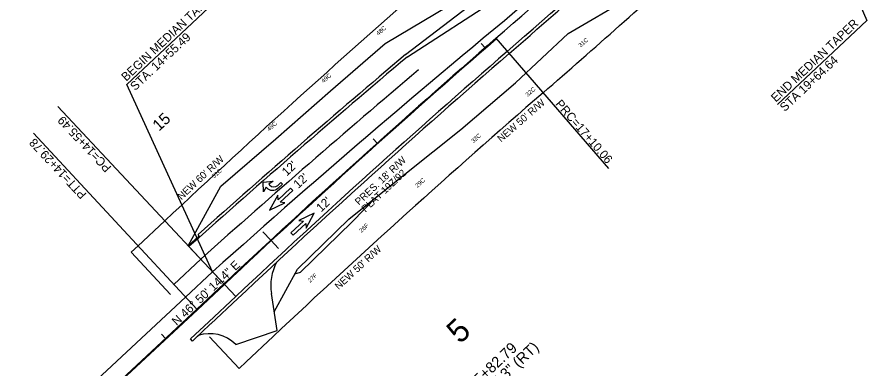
# Model space of a CAD drawing. Extents: x 1623239 to 1625698, y 1118659 to 1120751.
# Drawn here: x 1623812 to 1624403, y 1119168 to 1119413 of the extents above; entities that cross this region are included whole.
import ezdxf

# ---------------------------------------------------------------- set-up
doc = ezdxf.new("R2010")
doc.units = 0
for name, color, linetype in [('RD_EX_DV_TX_Prop', 7, 'Continuous'), ('RD_EX_RW_TX', 7, 'Continuous'), ('RD_HC_Cl', 7, 'Continuous'), ('RD_HC_CL_Rel', 7, 'Continuous'), ('RD_HC_Data', 7, 'Continuous'), ('RD_HC_Data_Tic', 7, 'Continuous'), ('RD_HC_TX_Sta50', 7, 'Continuous'), ('RD_PD_CstnLmt', 7, 'Continuous'), ('RD_PD_CstnLmt_TX', 7, 'Continuous'), ('RD_PD_DR_ErosCtrl', 7, 'Continuous'), ('RD_PD_Driveway', 7, 'Continuous'), ('RD_PD_Final_LnLine', 7, 'Continuous'), ('RD_PD_Final_TrvlWay', 7, 'Continuous'), ('RD_PD_Final_TX', 7, 'Continuous'), ('RD_PD_PaintMed', 7, 'Continuous'), ('RD_PD_PaveShd', 7, 'Continuous'), ('RD_PD_RW', 7, 'Continuous'), ('RD_PD_RW_TX', 7, 'Continuous')]:
    doc.layers.add(name, color=color, linetype=linetype)

# ---------------------------------------------------------------- blocks, each defined once
blk = doc.blocks.new('TARROW')
at = {"layer": 'RD_PD_Final_LnLine'}
for p, q in [((-3.29, -2.67), (-1.05, -2.34)), ((-1.05, -2.34), (-1.05, -3.09)), ((0.62, -3.09), (0.62, -2.5)), ((0.62, -2.5), (2.87, -3.17)), ((-3.3, -5.34), (-5.38, -5.34)), ((-5.38, -5.34), (-5.38, -6.34)), ((-5.38, -6.34), (-2.63, -6.34))]:
    blk.add_line(p, q, dxfattribs=at)
blk.add_lwpolyline([(2.87, -3.17), (0, 0), (-3.29, -2.67)], dxfattribs=at)
for centre, radius in [((-3.3, -3.09), 2.25), ((-2.63, -3.09), 3.25)]:
    blk.add_arc(centre, radius, 270, 0, dxfattribs=at)
blk = doc.blocks.new('RA Curved')
at = {"layer": 'RD_PD_Final_LnLine', "xscale": 1.0799984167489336, "yscale": -1.0799984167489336}
blk.add_blockref('TARROW', (6.14, -5.79), dxfattribs=at)

msp = doc.modelspace()

# ---------------------------------------------------------------- linework, layer by layer
at = {"layer": 'RD_HC_Cl'}
for p, q in [((1623937.25, 1119209.79), (1623956, 1119227.38)), ((1623608.84, 1118904.32), (1623937.25, 1119209.79))]:
    msp.add_line(p, q, dxfattribs=at)
at = {"layer": 'RD_HC_CL_Rel'}
for centre, start, end in [((1619901.34, 1124294.89), 310.911734, 313.16267), ((1628388.79, 1114500.77), 130.911734, 133.16267)]:
    msp.add_arc(centre, 6480, start, end, dxfattribs=at)
at = {"layer": 'RD_HC_Data'}
for p, q in [((1624145.06, 1119397.83), (1624223.3, 1119307.55)), ((1623956, 1119227.38), (1623840.61, 1119350.42)), ((1623937.25, 1119209.79), (1623823.59, 1119331.99))]:
    msp.add_line(p, q, dxfattribs=at)
at = {"layer": 'RD_HC_Data_Tic'}
for p, q in [((1624137.46, 1119391.24), (1624134.84, 1119394.26)), ((1624062.5, 1119325.05), (1624059.83, 1119328.03)), ((1623988.57, 1119257.72), (1623983.14, 1119263.59)), ((1623994, 1119251.84), (1623988.57, 1119257.72)), ((1623915.44, 1119189.51), (1623912.72, 1119192.44))]:
    msp.add_line(p, q, dxfattribs=at)
at = {"layer": 'RD_PD_CstnLmt'}
for p, q in [((1624195.36, 1119401.06), (1624239.51, 1119427.03)), ((1624068.03, 1119394.33), (1624112.11, 1119420.41)), ((1624158.63, 1119366.89), (1624195.36, 1119401.06)), ((1624029.97, 1119361.33), (1624068.03, 1119394.33)), ((1624120.76, 1119334.61), (1624158.63, 1119366.89)), ((1623992.2, 1119327.98), (1624029.97, 1119361.33)), ((1624081.79, 1119303.54), (1624120.76, 1119334.61)), ((1623953.89, 1119295.21), (1623992.2, 1119327.98)), ((1624042.89, 1119272.33), (1624081.79, 1119303.54)), ((1623931.22, 1119253.8), (1623953.89, 1119295.21)), ((1624007.14, 1119237.64), (1624042.89, 1119272.33)), ((1623990.97, 1119207.92), (1624007.14, 1119237.64))]:
    msp.add_line(p, q, dxfattribs=at)
at = {"layer": 'RD_PD_DR_ErosCtrl'}
for p, q in [((1624044.98, 1119270.18), (1624062.34, 1119287.94)), ((1624009.23, 1119235.49), (1624044.98, 1119270.18)), ((1624005.3, 1119234.26), (1624009.23, 1119235.49))]:
    msp.add_line(p, q, dxfattribs=at)
at = {"layer": 'RD_PD_Driveway'}
for p, q in [((1623993, 1119194.95), (1623988.97, 1119220.61)), ((1623964.25, 1119185.27), (1623993, 1119194.95)), ((1623934.07, 1119187.72), (1623938.06, 1119191.43))]:
    msp.add_line(p, q, dxfattribs=at)
for centre, radius, start, end in [((1624023.55, 1119226.04), 35, 152.24678, 188.93213), ((1623946.33, 1119167.84), 25, 44.19823, 109.30284)]:
    msp.add_arc(centre, radius, start, end, dxfattribs=at)
at = {"layer": 'RD_PD_Final_TrvlWay'}
for p, q in [((1624083.51, 1119385), (1624168.16, 1119439.74)), ((1623964.21, 1119218.62), (1623931.23, 1119253.79)), ((1623945.46, 1119201.04), (1623964.21, 1119218.62)), ((1623932.71, 1119189.18), (1623945.42, 1119201.01))]:
    msp.add_line(p, q, dxfattribs=at)
for centre, radius, start, end in [((1619901.34, 1124294.89), 6492, 310.911734, 313.16267), ((1628388.79, 1114500.77), 6468, 130.911734, 133.16267), ((1628628.65, 1113993.92), 7051.39, 130.133764, 131.766919)]:
    msp.add_arc(centre, radius, start, end, dxfattribs=at)
at = {"layer": 'RD_PD_Final_TX'}
for p, q in [((1624334.12, 1119568.29), (1624402.92, 1119410.28)), ((1623888.54, 1119365.77), (1623958.44, 1119431.32)), ((1624340.72, 1119351.94), (1624402.92, 1119410.28)), ((1623948.13, 1119235.77), (1623888.54, 1119365.77)), ((1624002.39, 1119293.91), (1623993.64, 1119285.7)), ((1623995.17, 1119284.06), (1624003.93, 1119292.27)), ((1624003.93, 1119292.27), (1624002.39, 1119293.91)), ((1623993.42, 1119289), (1623987.73, 1119278.62)), ((1623993.64, 1119285.7), (1623993.42, 1119289)), ((1623987.73, 1119278.62), (1623998.45, 1119283.64)), ((1623998.45, 1119283.64), (1623995.17, 1119284.06)), ((1624018.76, 1119276.45), (1624008.04, 1119271.44)), ((1624013.07, 1119266.08), (1624018.76, 1119276.45)), ((1624011.32, 1119271.01), (1624002.56, 1119262.8)), ((1624004.1, 1119261.16), (1624012.86, 1119269.37)), ((1624008.04, 1119271.44), (1624011.32, 1119271.01)), ((1624012.86, 1119269.37), (1624013.07, 1119266.08)), ((1624002.56, 1119262.8), (1624004.1, 1119261.16))]:
    msp.add_line(p, q, dxfattribs=at)
at = {"layer": 'RD_PD_PaintMed'}
for p, q in [((1623921.17, 1119226.93), (1623939.92, 1119244.52)), ((1623929.38, 1119218.18), (1623948.13, 1119235.77)), ((1623937.59, 1119209.43), (1623956.34, 1119227.01)), ((1623812.34, 1119109.31), (1623929.42, 1119218.21)), ((1623820.51, 1119100.53), (1623937.59, 1119209.43))]:
    msp.add_line(p, q, dxfattribs=at)
for centre, radius, start, end in [((1628628.65, 1113993.92), 7027.39, 129.270481, 131.762152), ((1628388.79, 1114500.77), 6479.5, 130.911734, 133.16267), ((1628628.65, 1113993.92), 7039.39, 130.133764, 131.762152)]:
    msp.add_arc(centre, radius, start, end, dxfattribs=at)
at = {"layer": 'RD_PD_PaveShd'}
for p, q in [((1624082.22, 1119386.53), (1624161.82, 1119447.48)), ((1623931.22, 1119253.8), (1623938.73, 1119260.81)), ((1623938.73, 1119260.81), (1623938.01, 1119261.57)), ((1623946.83, 1119199.58), (1623965.58, 1119217.17)), ((1623934.07, 1119187.72), (1623946.78, 1119199.54)), ((1623934.07, 1119187.72), (1623932.71, 1119189.18))]:
    msp.add_line(p, q, dxfattribs=at)
for centre, radius, start, end in [((1619901.34, 1124294.89), 6494, 310.911734, 312.721401), ((1628628.65, 1113993.92), 7053.39, 130.133764, 131.683852), ((1628388.79, 1114500.77), 6466, 130.911734, 133.16267)]:
    msp.add_arc(centre, radius, start, end, dxfattribs=at)
at = {"layer": 'RD_PD_RW'}
for p, q in [((1623896.2, 1119253.56), (1623914.95, 1119271.14)), ((1623891.59, 1119249.27), (1623896.38, 1119253.73)), ((1623918.83, 1119219.98), (1623891.59, 1119249.27)), ((1623966.51, 1119168.72), (1623946.07, 1119190.69)), ((1623971.38, 1119173.25), (1623990.2, 1119190.91)), ((1623966.51, 1119168.72), (1623971.38, 1119173.25))]:
    msp.add_line(p, q, dxfattribs=at)
for centre, radius, start, end in [((1619901.34, 1124294.89), 6530, 310.911734, 312.151971), ((1628388.79, 1114500.77), 6540, 130.911734, 133.16267), ((1628388.79, 1114500.77), 6430, 130.911734, 133.16267)]:
    msp.add_arc(centre, radius, start, end, dxfattribs=at)

# ---------------------------------------------------------------- block references
at = {"layer": 'RD_PD_RW_TX', "xscale": 1.4999999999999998, "yscale": 1.5, "rotation": -136.8373301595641}
msp.add_blockref('RA Curved', (1623996, 1119298.05), dxfattribs=at)

# ---------------------------------------------------------------- texts
at = {"layer": 'RD_EX_DV_TX_Prop'}
msp.add_text('5', height=16, rotation=43.16267, dxfattribs=at).set_placement((1624120.03, 1119185.15))
at = {"layer": 'RD_EX_RW_TX'}
for s, p in [("PRES. 18' R/W", (1624049.88, 1119281.61)), ('PLAT 19Z/92', (1624054.44, 1119276.75))]:
    msp.add_text(s, height=5, rotation=43.16267, dxfattribs=at).set_placement(p)
at = {"layer": 'RD_HC_Data'}
for s, height, rotation, p in [('PRC=17+10.06', 6, 310.91173, (1624185.92, 1119352.03)), ('PC=14+55.49', 6, 133.16267, (1623878.17, 1119308.34)), ('PTT=14+29.78', 6, 132.92763, (1623860.98, 1119289.76)), ('N 46%%d 50\' 14.4" E', 6, 43.16267, (1623923.23, 1119198.02)), ('P.I. = 15+82.79', 7.5, 43.16267, (1624110.37, 1119135.08)), ('    = 2%%d 15\' 3" (RT)', 7.5, 43.16267, (1624117.21, 1119127.79))]:
    msp.add_text(s, height=height, rotation=rotation, dxfattribs=at).set_placement(p)
at = {"layer": 'RD_HC_TX_Sta50'}
msp.add_text('15', height=8, rotation=42.92763, dxfattribs=at).set_placement((1623910.92, 1119332.98))
at = {"layer": 'RD_PD_CstnLmt_TX'}
for s, rotation, p in [('48C', 41.4428, (1624063.4, 1119399.58)), ('31C', 41.26486, (1624203.93, 1119391.29)), ('49C', 41.8849, (1624025.29, 1119366.54)), ('32C', 41.0007, (1624167.16, 1119357.08)), ('49C', 41.8849, (1623987.53, 1119333.19)), ('32C', 41.4428, (1624129.37, 1119324.87)), ('51C', 41.8849, (1623949.21, 1119300.42)), ('29C', 41.8849, (1624090.47, 1119293.87)), ('26F', 42.14906, (1624051.61, 1119262.69)), ('27F', 42.14906, (1624015.86, 1119228.01))]:
    msp.add_text(s, height=3, rotation=rotation, dxfattribs=at).set_placement(p)
at = {"layer": 'RD_PD_Final_TX'}
for s, rotation, p in [('BEGIN MEDIAN TAPER', 43.16253, (1623888.14, 1119367.66)), ('END MEDIAN TAPER', 43.16253, (1624339.59, 1119353.15)), ('STA. 14+55.49', 43.16253, (1623894.3, 1119361.1)), ('STA 19+64.64', 43.16253, (1624345.75, 1119346.58)), ("12'", 43.16341, (1623999.69, 1119301.78)), ("12'", 43.16341, (1624007.7, 1119293.24)), ("12'", 43.16341, (1624023.57, 1119276.85))]:
    msp.add_text(s, height=6, rotation=rotation, dxfattribs=at).set_placement(p)
at = {"layer": 'RD_PD_RW'}
msp.add_text("NEW 60' R/W", height=5, rotation=43.00383, dxfattribs=at).set_placement((1623926.49, 1119285.36))
at = {"layer": 'RD_PD_RW_TX'}
for rotation, p in [(41.18879, (1624148.7, 1119325.4)), (42.67004, (1624035.77, 1119223.04))]:
    msp.add_text("NEW 50' R/W", height=5, rotation=rotation, dxfattribs=at).set_placement(p)

doc.saveas('drawing.dxf')
